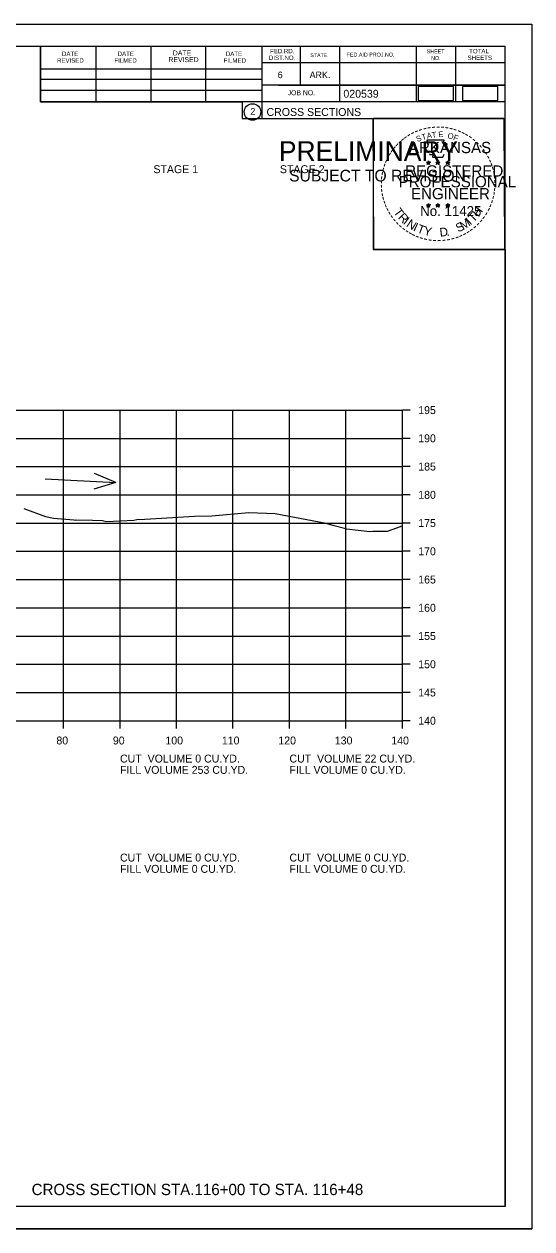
# Model space of a CAD drawing. Extents: x 915787 to 919910, y 133456 to 136717.
# Drawn here: x 916487 to 916576.9, y 135162.7 to 135376.1 of the extents above; entities that cross this region are included whole.
import ezdxf

# ---------------------------------------------------------------- set-up
doc = ezdxf.new("R2010")
doc.units = 0
for name, color, linetype in [('R_Axis', 7, 'Continuous'), ('R_Axis Annot', 7, 'Continuous'), ('R_Border', 7, 'Continuous'), ('R_Border Notes', 7, 'Continuous'), ('R_Border PE', 7, 'Continuous'), ('R_Border Prem', 7, 'Continuous'), ('R_Draft', 7, 'Continuous'), ('R_Exist Surface', 7, 'Continuous'), ('R_Grid', 7, 'Continuous'), ('R_No Plot', 7, 'Continuous'), ('R_Water Annot', 7, 'Continuous'), ('R_Xsect Slope', 7, 'Continuous')]:
    doc.layers.add(name, color=color, linetype=linetype)

msp = doc.modelspace()

# ---------------------------------------------------------------- linework, layer by layer
at = {"layer": 'R_Axis'}
for p, q in [((916553.98, 135252.72), (916553.98, 135307.72)), ((916555.38, 135307.72), (916553.98, 135307.72)), ((916555.38, 135302.72), (916553.98, 135302.72)), ((916555.38, 135297.72), (916553.98, 135297.72)), ((916555.38, 135292.72), (916553.98, 135292.72)), ((916555.38, 135287.72), (916553.98, 135287.72)), ((916555.38, 135282.72), (916553.98, 135282.72)), ((916555.38, 135277.72), (916553.98, 135277.72)), ((916555.38, 135272.72), (916553.98, 135272.72)), ((916555.38, 135267.72), (916553.98, 135267.72)), ((916555.38, 135262.72), (916553.98, 135262.72)), ((916555.38, 135257.72), (916553.98, 135257.72)), ((916273.98, 135252.72), (916553.98, 135252.72)), ((916493.98, 135251.32), (916493.98, 135252.72)), ((916503.98, 135251.32), (916503.98, 135252.72)), ((916513.98, 135251.32), (916513.98, 135252.72)), ((916523.98, 135251.32), (916523.98, 135252.72)), ((916533.98, 135251.32), (916533.98, 135252.72)), ((916543.98, 135251.32), (916543.98, 135252.72)), ((916553.98, 135251.32), (916553.98, 135252.72)), ((916555.38, 135252.72), (916553.98, 135252.72))]:
    msp.add_line(p, q, dxfattribs=at)
at = {"layer": 'R_Border'}
for p, q in [((916255.98, 135372.18), (916572.16, 135372.18)), ((916489.9, 135362.3), (916489.9, 135372.18)), ((916499.76, 135362.3), (916499.76, 135371.98)), ((916509.52, 135362.3), (916509.52, 135371.98)), ((916519.2, 135362.3), (916519.2, 135371.98)), ((916529.06, 135372.18), (916529.06, 135359.38)), ((916535.9, 135372.18), (916535.9, 135365.24)), ((916542.84, 135372.18), (916542.84, 135362.3)), ((916556.42, 135372.18), (916556.42, 135362.3)), ((916563.36, 135372.18), (916563.36, 135362.3)), ((916572.16, 135166.72), (916572.16, 135372.18)), ((916572.16, 135369.24), (916529.06, 135369.24)), ((916572.16, 135369.26), (916572.16, 135369.26)), ((916489.9, 135368.16), (916529.06, 135368.16)), ((916489.9, 135366.3), (916529.06, 135366.3)), ((916572.16, 135365.24), (916529.06, 135365.24)), ((916532.02, 135365.24), (916572.16, 135365.24)), ((916489.9, 135362.3), (916489.9, 135364.36)), ((916489.9, 135364.36), (916529.06, 135364.36)), ((916572.16, 135362.3), (916489.9, 135362.3)), ((916529.06, 135359.38), (916572.16, 135359.38)), ((916572.16, 135166.72), (916255.98, 135166.72))]:
    msp.add_line(p, q, dxfattribs=at)
msp.add_circle((916527.44, 135360.51), 1.47, dxfattribs=at)
at = {"layer": 'R_Border PE'}
for p, q in [((916558.24, 135351.63), (916558.59, 135351.52)), ((916558.24, 135351.63), (916558.49, 135351.59)), ((916558.24, 135351.63), (916558.48, 135351.51)), ((916558.37, 135351.23), (916558.59, 135351.52)), ((916558.37, 135351.23), (916558.5, 135351.47)), ((916558.37, 135351.23), (916558.59, 135351.44)), ((916558.59, 135351.89), (916558.55, 135351.64)), ((916558.59, 135351.52), (916558.59, 135351.89)), ((916558.59, 135351.89), (916558.64, 135351.64)), ((916558.94, 135351.63), (916558.59, 135351.52)), ((916558.8, 135351.23), (916558.59, 135351.52)), ((916558.8, 135351.23), (916558.59, 135351.44)), ((916558.94, 135351.63), (916558.65, 135351.58)), ((916558.8, 135351.23), (916558.66, 135351.52)), ((916558.94, 135351.63), (916558.73, 135351.53)), ((916559.91, 135351.63), (916560.26, 135351.52)), ((916559.91, 135351.63), (916560.16, 135351.59)), ((916559.91, 135351.63), (916560.15, 135351.51)), ((916560.04, 135351.23), (916560.26, 135351.52)), ((916560.04, 135351.23), (916560.17, 135351.47)), ((916560.04, 135351.23), (916560.26, 135351.44)), ((916560.26, 135351.89), (916560.22, 135351.64)), ((916560.26, 135351.52), (916560.26, 135351.89)), ((916560.26, 135351.89), (916560.31, 135351.64)), ((916560.61, 135351.63), (916560.26, 135351.52)), ((916560.47, 135351.23), (916560.26, 135351.52)), ((916560.47, 135351.23), (916560.26, 135351.44)), ((916560.61, 135351.63), (916560.32, 135351.58)), ((916560.47, 135351.23), (916560.33, 135351.52)), ((916560.61, 135351.63), (916560.4, 135351.53)), ((916561.67, 135351.62), (916562.02, 135351.51)), ((916561.67, 135351.62), (916561.93, 135351.58)), ((916561.67, 135351.62), (916561.91, 135351.5)), ((916561.81, 135351.21), (916562.02, 135351.51)), ((916561.81, 135351.21), (916561.93, 135351.46)), ((916561.81, 135351.21), (916562.02, 135351.43)), ((916562.02, 135351.88), (916561.98, 135351.62)), ((916562.02, 135351.51), (916562.02, 135351.88)), ((916562.02, 135351.88), (916562.07, 135351.63)), ((916562.37, 135351.62), (916562.02, 135351.51)), ((916562.24, 135351.21), (916562.02, 135351.51)), ((916562.24, 135351.21), (916562.02, 135351.43)), ((916562.37, 135351.62), (916562.08, 135351.57)), ((916562.24, 135351.21), (916562.1, 135351.5)), ((916562.37, 135351.62), (916562.17, 135351.52)), ((916558.24, 135344.06), (916558.58, 135343.95)), ((916558.24, 135344.06), (916558.49, 135344.02)), ((916558.24, 135344.06), (916558.47, 135343.94)), ((916558.37, 135343.65), (916558.58, 135343.95)), ((916558.37, 135343.65), (916558.49, 135343.9)), ((916558.37, 135343.65), (916558.58, 135343.87)), ((916558.58, 135344.31), (916558.54, 135344.06)), ((916558.58, 135343.95), (916558.58, 135344.31)), ((916558.58, 135344.31), (916558.63, 135344.06)), ((916558.93, 135344.06), (916558.58, 135343.95)), ((916558.8, 135343.65), (916558.58, 135343.95)), ((916558.8, 135343.65), (916558.58, 135343.87)), ((916558.93, 135344.06), (916558.65, 135344.01)), ((916558.8, 135343.65), (916558.66, 135343.94)), ((916558.93, 135344.06), (916558.73, 135343.96)), ((916559.9, 135344.06), (916560.25, 135343.95)), ((916559.9, 135344.06), (916560.16, 135344.02)), ((916559.9, 135344.06), (916560.14, 135343.94)), ((916560.04, 135343.65), (916560.25, 135343.95)), ((916560.04, 135343.65), (916560.16, 135343.9)), ((916560.04, 135343.65), (916560.25, 135343.87)), ((916560.25, 135344.31), (916560.21, 135344.06)), ((916560.25, 135343.95), (916560.25, 135344.31)), ((916560.25, 135344.31), (916560.3, 135344.06)), ((916560.6, 135344.06), (916560.25, 135343.95)), ((916560.47, 135343.65), (916560.25, 135343.95)), ((916560.47, 135343.65), (916560.25, 135343.87)), ((916560.6, 135344.06), (916560.31, 135344.01)), ((916560.47, 135343.65), (916560.33, 135343.94)), ((916560.6, 135344.06), (916560.4, 135343.96)), ((916561.67, 135344.05), (916562.02, 135343.94)), ((916561.67, 135344.05), (916561.92, 135344.01)), ((916561.67, 135344.05), (916561.91, 135343.93)), ((916561.8, 135343.64), (916562.02, 135343.94)), ((916561.8, 135343.64), (916561.93, 135343.89)), ((916561.8, 135343.64), (916562.02, 135343.86)), ((916562.02, 135344.3), (916561.98, 135344.05)), ((916562.02, 135343.94), (916562.02, 135344.3)), ((916562.02, 135344.3), (916562.07, 135344.05)), ((916562.37, 135344.05), (916562.02, 135343.94)), ((916562.23, 135343.64), (916562.02, 135343.94)), ((916562.23, 135343.64), (916562.02, 135343.86)), ((916562.37, 135344.05), (916562.08, 135344)), ((916562.23, 135343.64), (916562.1, 135343.93)), ((916562.37, 135344.05), (916562.16, 135343.95))]:
    msp.add_line(p, q, dxfattribs=at)
for points in [[(916558.28, 135355.51), (916558.55, 135354.68)], [(916561.79, 135354.59), (916561.93, 135354.87), (916561.25, 135354.85), (916561.4, 135355.51), (916558.28, 135355.51)], [(916558.77, 135353.09), (916558.77, 135353), (916559.34, 135352.98), (916559.28, 135352.51), (916561.15, 135352.51), (916561.35, 135353.05)], [(916558.59, 135351.89), (916558.8, 135351.23), (916558.24, 135351.63), (916558.94, 135351.63), (916558.37, 135351.23), (916558.59, 135351.89)], [(916560.26, 135351.89), (916560.47, 135351.23), (916559.91, 135351.63), (916560.61, 135351.63), (916560.04, 135351.23), (916560.26, 135351.89)], [(916562.02, 135351.88), (916562.24, 135351.21), (916561.67, 135351.62), (916562.37, 135351.62), (916561.81, 135351.21), (916562.02, 135351.88)], [(916558.58, 135344.31), (916558.8, 135343.65), (916558.24, 135344.06), (916558.93, 135344.06), (916558.37, 135343.65), (916558.58, 135344.31)], [(916560.25, 135344.31), (916560.47, 135343.65), (916559.9, 135344.06), (916560.6, 135344.06), (916560.04, 135343.65), (916560.25, 135344.31)], [(916562.02, 135344.3), (916562.23, 135343.64), (916561.67, 135344.05), (916562.37, 135344.05), (916561.8, 135343.64), (916562.02, 135344.3)]]:
    msp.add_lwpolyline(points, dxfattribs=at)
for centre, radius in [((916558.59, 135351.52), 0.172), ((916558.59, 135351.52), 0.145), ((916558.59, 135351.52), 0.116), ((916558.59, 135351.52), 0.0991), ((916558.59, 135351.52), 0.0747), ((916558.59, 135351.52), 0.0495), ((916558.59, 135351.52), 0.0296), ((916560.26, 135351.52), 0.172), ((916560.26, 135351.52), 0.145), ((916560.26, 135351.52), 0.116), ((916560.26, 135351.52), 0.0991), ((916560.26, 135351.52), 0.0747), ((916560.26, 135351.52), 0.0495), ((916560.26, 135351.52), 0.0296), ((916562.02, 135351.51), 0.172), ((916562.02, 135351.51), 0.145), ((916562.02, 135351.51), 0.116), ((916562.02, 135351.51), 0.0991), ((916562.02, 135351.51), 0.0747), ((916562.02, 135351.51), 0.0495), ((916562.02, 135351.51), 0.0296), ((916558.58, 135343.95), 0.172), ((916558.58, 135343.95), 0.145), ((916558.58, 135343.95), 0.116), ((916558.58, 135343.95), 0.0991), ((916558.58, 135343.95), 0.0747), ((916558.58, 135343.95), 0.0495), ((916558.58, 135343.95), 0.0296), ((916560.25, 135343.95), 0.172), ((916560.25, 135343.95), 0.145), ((916560.25, 135343.95), 0.116), ((916560.25, 135343.95), 0.0991), ((916560.25, 135343.95), 0.0747), ((916560.25, 135343.95), 0.0495), ((916560.25, 135343.95), 0.0296), ((916562.02, 135343.94), 0.172), ((916562.02, 135343.94), 0.145), ((916562.02, 135343.94), 0.116), ((916562.02, 135343.94), 0.0991), ((916562.02, 135343.94), 0.0747), ((916562.02, 135343.94), 0.0495), ((916562.02, 135343.94), 0.0296)]:
    msp.add_circle(centre, radius, dxfattribs=at)
at = {"layer": 'R_Exist Surface'}
msp.add_lwpolyline([(916486.93, 135290.29), (916490.78, 135288.9), (916492.17, 135288.6), (916495.81, 135288.29), (916496.06, 135288.25), (916496.19, 135288.29), (916499.13, 135288.24), (916500.9, 135288.17), (916501.61, 135288.02), (916506.41, 135288.26), (916506.98, 135288.38), (916508.36, 135288.43), (916517.17, 135288.97), (916520.24, 135289), (916526.8, 135289.57), (916531.46, 135289.42), (916540.5, 135287.69), (916540.58, 135287.68), (916540.6, 135287.67), (916541.68, 135287.37), (916543.95, 135286.73), (916543.97, 135286.72), (916544.05, 135286.72), (916548.22, 135286.25), (916548.75, 135286.27), (916551.33, 135286.29), (916552.98, 135286.9), (916553.95, 135287.24), (916553.98, 135287.25)], dxfattribs=at)
at = {"layer": 'R_Grid'}
for p, q in [((916273.98, 135307.72), (916553.98, 135307.72)), ((916493.98, 135252.72), (916493.98, 135307.72)), ((916503.98, 135252.72), (916503.98, 135307.72)), ((916513.98, 135252.72), (916513.98, 135307.72)), ((916523.98, 135252.72), (916523.98, 135307.72)), ((916533.98, 135252.72), (916533.98, 135307.72)), ((916543.98, 135252.72), (916543.98, 135307.72)), ((916553.98, 135252.72), (916553.98, 135307.72)), ((916273.98, 135302.72), (916553.98, 135302.72)), ((916273.98, 135297.72), (916553.98, 135297.72)), ((916273.98, 135292.72), (916553.98, 135292.72)), ((916273.98, 135287.72), (916553.98, 135287.72)), ((916273.98, 135282.72), (916553.98, 135282.72)), ((916273.98, 135277.72), (916553.98, 135277.72)), ((916273.98, 135272.72), (916553.98, 135272.72)), ((916273.98, 135267.72), (916553.98, 135267.72)), ((916273.98, 135262.72), (916553.98, 135262.72)), ((916273.98, 135257.72), (916553.98, 135257.72)), ((916273.98, 135252.72), (916553.98, 135252.72))]:
    msp.add_line(p, q, dxfattribs=at)
at = {"layer": 'R_No Plot'}
for p, q in [((916243.57, 135376.07), (916576.91, 135376.07)), ((916548.19, 135336.92), (916548.19, 135336.92)), ((916243.57, 135162.74), (916576.91, 135162.74))]:
    msp.add_line(p, q, dxfattribs=at)
for points in [[(916243.57, 135376.07), (916576.91, 135376.07), (916576.91, 135162.74), (916243.57, 135162.74)], [(916489.9, 135372.18), (916489.9, 135362.3), (916525.63, 135362.3), (916525.63, 135359.38), (916548.83, 135359.38), (916548.83, 135336.16), (916572.16, 135336.16), (916572.16, 135166.72), (916255.98, 135166.72), (916255.98, 135372.18)], [(916548.83, 135359.41), (916571.92, 135359.41), (916572.04, 135336.16), (916548.94, 135336.16)]]:
    msp.add_lwpolyline(points, close=True, dxfattribs=at)
at = {"layer": 'R_Water Annot'}
for p, q in [((916490.7, 135295.53), (916503.25, 135294.92)), ((916503.25, 135294.92), (916499.34, 135293.71)), ((916503.25, 135294.92), (916499.48, 135296.51))]:
    msp.add_line(p, q, dxfattribs=at)
at = {"layer": 'R_Xsect Slope'}
for points in [[(916556.77, 135362.56), (916563.02, 135362.56), (916563.02, 135365.03), (916556.77, 135365.03)], [(916564.61, 135362.56), (916570.86, 135362.56), (916570.86, 135365.04), (916564.61, 135365.04)]]:
    msp.add_lwpolyline(points, close=True, dxfattribs=at)

# ---------------------------------------------------------------- texts
at = {"layer": 'R_Axis Annot'}
for s, p in [('195', (916556.78, 135307.02)), ('190', (916556.78, 135302.02)), ('185', (916556.78, 135297.02)), ('180', (916556.78, 135292.02)), ('175', (916556.78, 135287.02)), ('170', (916556.78, 135282.02)), ('165', (916556.78, 135277.02)), ('160', (916556.78, 135272.02)), ('155', (916556.78, 135267.02)), ('150', (916556.78, 135262.02)), ('145', (916556.78, 135257.02)), ('140', (916556.78, 135252.02)), ('80', (916492.71, 135248.52)), ('90', (916502.71, 135248.52)), ('100', (916512.01, 135248.52)), ('110', (916522.01, 135248.52)), ('120', (916532.01, 135248.52)), ('130', (916542.01, 135248.52)), ('140', (916552.01, 135248.52))]:
    msp.add_text(s, height=1.4, dxfattribs=at).set_placement(p)
at = {"layer": 'R_Border'}
for s, height, p in [('DATE', 0.879, (916513.34, 135370.52)), ('FED.RD.', 0.782, (916530.54, 135370.9)), ('SHEET', 0.684, (916558.28, 135370.9)), ('TOTAL', 0.782, (916565.8, 135370.9)), ('REVISED', 0.782, (916492.82, 135369.24)), ('DATE', 0.782, (916493.7, 135370.42)), ('FILMED', 0.782, (916502.98, 135369.24)), ('DATE', 0.782, (916503.56, 135370.42)), ('REVISED', 0.879, (916512.56, 135369.34)), ('FILMED', 0.782, (916522.32, 135369.24)), ('DATE', 0.782, (916522.72, 135370.42)), ('DIST.NO.', 0.782, (916530.34, 135369.72)), ('STATE', 0.684, (916537.66, 135370.22)), ('FED.AID PROJ.NO.', 0.684, (916544.12, 135370.32)), ('NO.', 0.684, (916559.06, 135369.72)), ('SHEETS', 0.782, (916565.52, 135369.72)), ('6', 1.17, (916531.9, 135366.5)), ('ARK.', 1.172, (916537.56, 135366.5)), ('JOB NO.', 0.879, (916533.66, 135363.48)), ('020539', 1.4, (916543.53, 135363.04)), ('2', 1.17, (916527.06, 135360.03)), ('CROSS SECTIONS', 1.4, (916529.92, 135359.81))]:
    msp.add_text(s, height=height, rotation=360, dxfattribs=at).set_placement(p)
at = {"layer": 'R_Border Notes'}
for s, p in [('STAGE 1', (916509.89, 135349.68)), ('STAGE 2', (916532.29, 135349.68)), ('CUT  VOLUME 0 CU.YD.', (916503.98, 135245.32)), ('CUT  VOLUME 22 CU.YD.', (916533.98, 135245.32)), ('FILL VOLUME 253 CU.YD.', (916503.98, 135243.32)), ('FILL VOLUME 0 CU.YD.', (916533.98, 135243.32)), ('CUT  VOLUME 0 CU.YD.', (916503.98, 135227.79)), ('CUT  VOLUME 0 CU.YD.', (916533.98, 135227.79)), ('FILL VOLUME 0 CU.YD.', (916503.98, 135225.79)), ('FILL VOLUME 0 CU.YD.', (916533.98, 135225.79))]:
    msp.add_text(s, height=1.4, dxfattribs=at).set_placement(p)
at = {"layer": 'R_Border PE'}
for s, height, rotation, p in [('-', 1.6, 34.0636, (916555.16, 135355.68)), ('-', 1.6, 28.7918, (916555.76, 135356.05)), ('-', 1.6, 24.3072, (916556.39, 135356.37)), ('S', 1, 21.594, (916556.64, 135355.19)), ('-', 1.6, 19.1761, (916557.03, 135356.64)), ('T', 1, 16.4036, (916557.55, 135355.52)), ('-', 1.6, 13.6301, (916557.78, 135356.88)), ('A', 1, 11.2132, (916558.38, 135355.77)), ('-', 1.6, 10.2193, (916558.46, 135357.04)), ('T', 1, 6.0228, (916559.22, 135355.94)), ('-', 1.6, 5.8968, (916559.19, 135357.15)), ('-', 1.6, 0.1862, (916559.96, 135357.22)), ('E', 1, 0.8323, (916560.33, 135356.05)), ('-', 1.6, 357.743, (916560.68, 135357.21)), ('-', 1.6, 352.1617, (916561.42, 135357.15)), ('O', 1, 350.4515, (916561.93, 135355.84)), ('-', 1.6, 347.2049, (916562.14, 135357.04)), ('F', 1, 340.0707, (916562.89, 135355.61)), ('-', 1.6, 342.3362, (916562.78, 135356.89)), ('-', 1.6, 337.8551, (916563.51, 135356.66)), ('-', 1.6, 334.1211, (916564.14, 135356.39)), ('-', 1.6, 329.6409, (916564.72, 135356.11)), ('-', 1.6, 50.6142, (916552.83, 135353.53)), ('-', 1.6, 48.423, (916553.23, 135354.01)), ('-', 1.6, 42.9622, (916553.68, 135354.49)), ('-', 1.6, 38.9507, (916554.11, 135354.91)), ('-', 1.6, 36.2317, (916554.59, 135355.29)), ('ARKANSAS', 2, 360, (916555.13, 135353.22)), ('-', 1.6, 325.8627, (916565.37, 135355.75)), ('-', 1.6, 320.5297, (916565.98, 135355.32)), ('-', 1.6, 315.5786, (916566.58, 135354.83)), ('-', 1.6, 309.8797, (916567.14, 135354.28)), ('-', 1.6, 67.7743, (916551.52, 135351.21)), ('-', 1.6, 62.8713, (916551.78, 135351.82)), ('-', 1.6, 58.0706, (916552.09, 135352.43)), ('-', 1.6, 54.2325, (916552.41, 135352.96)), ('-', 1.6, 306.6522, (916567.67, 135353.68)), ('-', 1.4, 303.6753, (916568.16, 135353.11)), ('-', 1.6, 299.6684, (916568.47, 135352.51)), ('-', 1.6, 294.6628, (916568.8, 135351.89)), ('-', 1.6, 75.461, (916551.1, 135349.87)), ('-', 1.6, 72.3945, (916551.3, 135350.58)), ('REGISTERED', 2, 360, (916554.46, 135349.07)), ('DWB', 0.01, 360, (916558.58, 135351.52)), ('DWB', 0.01, 360, (916560.25, 135351.52)), ('DWB', 0.01, 360, (916562.01, 135351.51)), ('-', 1.6, 290.5728, (916569.06, 135351.32)), ('-', 1.6, 285.1233, (916569.29, 135350.74)), ('-', 1.6, 280.5493, (916569.49, 135350)), ('-', 1.6, 89.0622, (916550.87, 135347.76)), ('-', 1.6, 85.1863, (916550.89, 135348.46)), ('-', 1.6, 81.2013, (916550.97, 135349.15)), ('PROFESSIONAL', 2, 360, (916553.31, 135347.17)), ('-', 1.6, 276.5962, (916569.65, 135349.23)), ('-', 1.6, 274.3301, (916569.71, 135348.51)), ('-', 1.6, 269.9407, (916569.75, 135347.87)), ('-', 1.6, 94.1959, (916550.9, 135347.04)), ('-', 1.6, 98.9479, (916550.97, 135346.37)), ('-', 1.6, 101.7149, (916551.11, 135345.64)), ('ENGINEER', 2, 360, (916555.49, 135345.05)), ('-', 1.6, 255.7626, (916569.55, 135345.88)), ('-', 1.6, 260.9953, (916569.66, 135346.55)), ('-', 1.6, 263.5172, (916569.73, 135347.21)), ('-', 1.6, 105.4578, (916551.27, 135345.04)), ('-', 1.6, 109.0874, (916551.49, 135344.41)), ('-', 1.6, 114.0643, (916551.74, 135343.81)), ('-', 1.6, 115.7289, (916552.05, 135343.2)), ('T', 1.54, 306.0406, (916552.34, 135342.79)), ('No. 11425', 1.757, 360, (916557.12, 135342.09)), ('DWB', 0.01, 360, (916558.57, 135343.94)), ('DWB', 0.01, 360, (916560.24, 135343.95)), ('DWB', 0.01, 360, (916562.01, 135343.94)), ('H', 1.54, 54.6088, (916567.46, 135341.82)), ('-', 1.6, 244.6197, (916568.88, 135343.85)), ('-', 1.6, 247.8887, (916569.14, 135344.48)), ('-', 1.6, 252.8681, (916569.36, 135345.16)), ('-', 1.6, 120.4471, (916552.4, 135342.61)), ('-', 1.6, 125.8934, (916552.81, 135342.05)), ('-', 1.6, 130.7181, (916553.27, 135341.5)), ('R', 1.54, 314.005, (916553.11, 135341.74)), ('I', 1.54, 321.9694, (916554.01, 135340.81)), ('N', 1.54, 326.5002, (916554.57, 135340.34)), ('M', 1.54, 32.6563, (916564.73, 135339.56)), ('I', 1.54, 42.1136, (916566.01, 135340.4)), ('T', 1.54, 46.6444, (916566.58, 135340.88)), ('-', 1.6, 231.2538, (916567.65, 135341.88)), ('-', 1.6, 233.8452, (916568.08, 135342.45)), ('-', 1.6, 239.0712, (916568.49, 135343.1)), ('-', 1.6, 134.2238, (916553.78, 135340.95)), ('-', 1.6, 138.9338, (916554.31, 135340.49)), ('-', 1.6, 144.6463, (916554.87, 135340.08)), ('-', 1.6, 148.0898, (916555.43, 135339.71)), ('I', 1.54, 335.3603, (916555.78, 135339.55)), ('T', 1.54, 339.8912, (916556.44, 135339.22)), ('Y', 1.54, 347.8556, (916557.66, 135338.78)), ('D', 1.54, 6.3969, (916560.65, 135338.42)), ('S', 1.54, 26.9312, (916563.89, 135339.15)), ('-', 1.6, 212.2491, (916565.57, 135339.95)), ('-', 1.6, 215.7363, (916566.1, 135340.34)), ('-', 1.6, 221.0851, (916566.65, 135340.81)), ('-', 1.6, 225.7653, (916567.17, 135341.32)), ('-', 1.6, 151.5704, (916556.01, 135339.39)), ('-', 1.6, 154.6002, (916556.53, 135339.14)), ('-', 1.6, 158.5612, (916557.15, 135338.88)), ('-', 1.6, 162.7983, (916557.84, 135338.67)), ('-', 1.6, 167.5555, (916558.55, 135338.51)), ('-', 1.6, 173.1155, (916559.33, 135338.4)), ('-', 1.6, 176.5183, (916560.07, 135338.34)), ('-', 1.6, 181.5918, (916560.82, 135338.36)), ('-', 1.6, 185.8167, (916561.63, 135338.44)), ('-', 1.6, 191.2858, (916562.36, 135338.57)), ('.', 1.54, 13.7642, (916561.84, 135338.55)), ('-', 1.6, 195.4743, (916563.09, 135338.77)), ('-', 1.6, 200.7184, (916563.77, 135339.01)), ('-', 1.6, 204.2516, (916564.39, 135339.29)), ('-', 1.6, 207.3568, (916565.01, 135339.6))]:
    msp.add_text(s, height=height, rotation=rotation, dxfattribs=at).set_placement(p)
at = {"layer": 'R_Border Prem'}
for s, height, p in [('PRELIMINARY', 3.5, (916532.11, 135351.84)), ('DWB', 0.01, (916532.85, 135353.69)), ('SUBJECT TO REVISION', 2.0751, (916533.92, 135348.21))]:
    msp.add_text(s, height=height, rotation=360, dxfattribs=at).set_placement(p)
at = {"layer": 'R_Draft'}
msp.add_text('CROSS SECTION STA.116+00 TO STA. 116+48', height=2, dxfattribs=at).set_placement((916488.33, 135168.72))

doc.saveas('drawing.dxf')
